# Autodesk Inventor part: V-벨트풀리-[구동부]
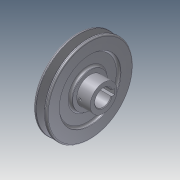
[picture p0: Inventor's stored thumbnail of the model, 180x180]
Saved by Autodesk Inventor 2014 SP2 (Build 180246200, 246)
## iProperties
Company: 한국ATC센터
Created: 2014-10
Part Number: V-벨트풀리-[구동부]
Document SubType Name: Modeling
Designer: 한국ATC센터
Density: 7.86 g/cm^3
Material: 강, 연강
Mass: 1515.01 g
Surface Area: 468.111 cm^2
Volume: 192.75 cm^3
Appearance: 강철
Author: KYOUNG IL JANG
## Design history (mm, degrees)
sketch "스케치1"
  geometry: L1 (-20, 0)-(20, 0); L2 (-20, 0)-(-20, 26); L3 (-20, 26)-(-16, 26); L4 (-16, 26)-(-16, 46); L5 (-16, 46)-(-20, 46); L6 (-20, 46)-(-20, 64.5); L7 (-20, 64.5)-(-16.062, 64.5); L8 (-16.062, 64.5)-(-12.001, 52); L9 (-12.001, 52)-(-7.999, 52); L10 (-7.999, 52)-(-3.938, 64.5); L11 (-3.938, 64.5)-(0, 64.5); L12 (0, 64.5)-(0, 46); L13 (0, 46)-(-4, 46); L14 (-4, 46)-(-4, 26); L15 (-4, 26)-(0, 26); L16 (0, 26)-(0, 20); L17 (0, 20)-(20, 20); L18 (20, 20)-(20, 0); L19 (-14.6, 60)-(-5.4, 60); 2 further points
  constraints: 38 end point, 11 parallel, 7 collinear, 3 equal length, 3 perpendicular, 2 point on line, 1 coincident, 1 horizontal, 1 midpoint
  dimensions: "d0" = 40 distance of L1.start L1.end; "d1" = 4.5 distance between parallel lines of L7 L19; "d2" = 8 distance between parallel lines of L9 L19; "d3" = 9.2 distance of L19.start L19.end; "d4" = 36 deg angle of L10 L8; "d5" = 20 distance between parallel lines of L12 L6; "d6" = 120 diameter of L19 L1; "d7" = 4 distance of L2.end L3.end; "d8" = 52 diameter of L3 L1; "d9" = 92 diameter of L5 L1; "d10" = 40 diameter of L17 L1
revolve "회전1" sketch "스케치1" stored, may be unused: angle "d11" = 90 deg
sketch "스케치2"
  geometry: L1 (-4, 11.843)-(-4, 16.5); L2 (-4, 16.5)-(4, 16.5); L3 (4, 16.5)-(4, 11.843); A1 r 12.5 centre (0, 0) between (-4, 11.843) and (4, 11.843); 1 further point
  constraints: 6 end point, 2 parallel, 2 point on circle, 1 centre point, 1 coincident, 1 horizontal, 1 vertical
  dimensions: "d12" = 25 diameter of A1; "d13" = 8 distance of L1.end L2.end; "d14" = 29 dimension on A1 L2
extrude "돌출1" cut sketch "스케치2" stored distance "d15" = 10; taper "d16" = 0 deg
chamfer "모따기1" distance "d17" = 1; stored, may be unused: second distance "d18" = 2, angle "d19" = 45 deg
node "작업 평면1"
sketch "스케치3"
  geometry: L1 (10, -20)-(10, 20) reference; 3 further points
  constraints: 1 horizontal alignment, 1 midpoint
  dimensions: "d20" = 15 distance from line of L1 point (-5, 0)
hole "구멍1" sketch "스케치3" at (-5, 0) diameter "d21" = 4.459; stored, may be unused: countersink angle "d25" = 90 deg, drill point angle "d27" = 118 deg; dims "d22" = 6, "d23" = 4, "d24" = 2, "d26" = 8
fillet "모깎기1" dims "d28" = 3, "d29" = 2, "d30" = 0.5, "d31" = 1
node "솔리드1"
